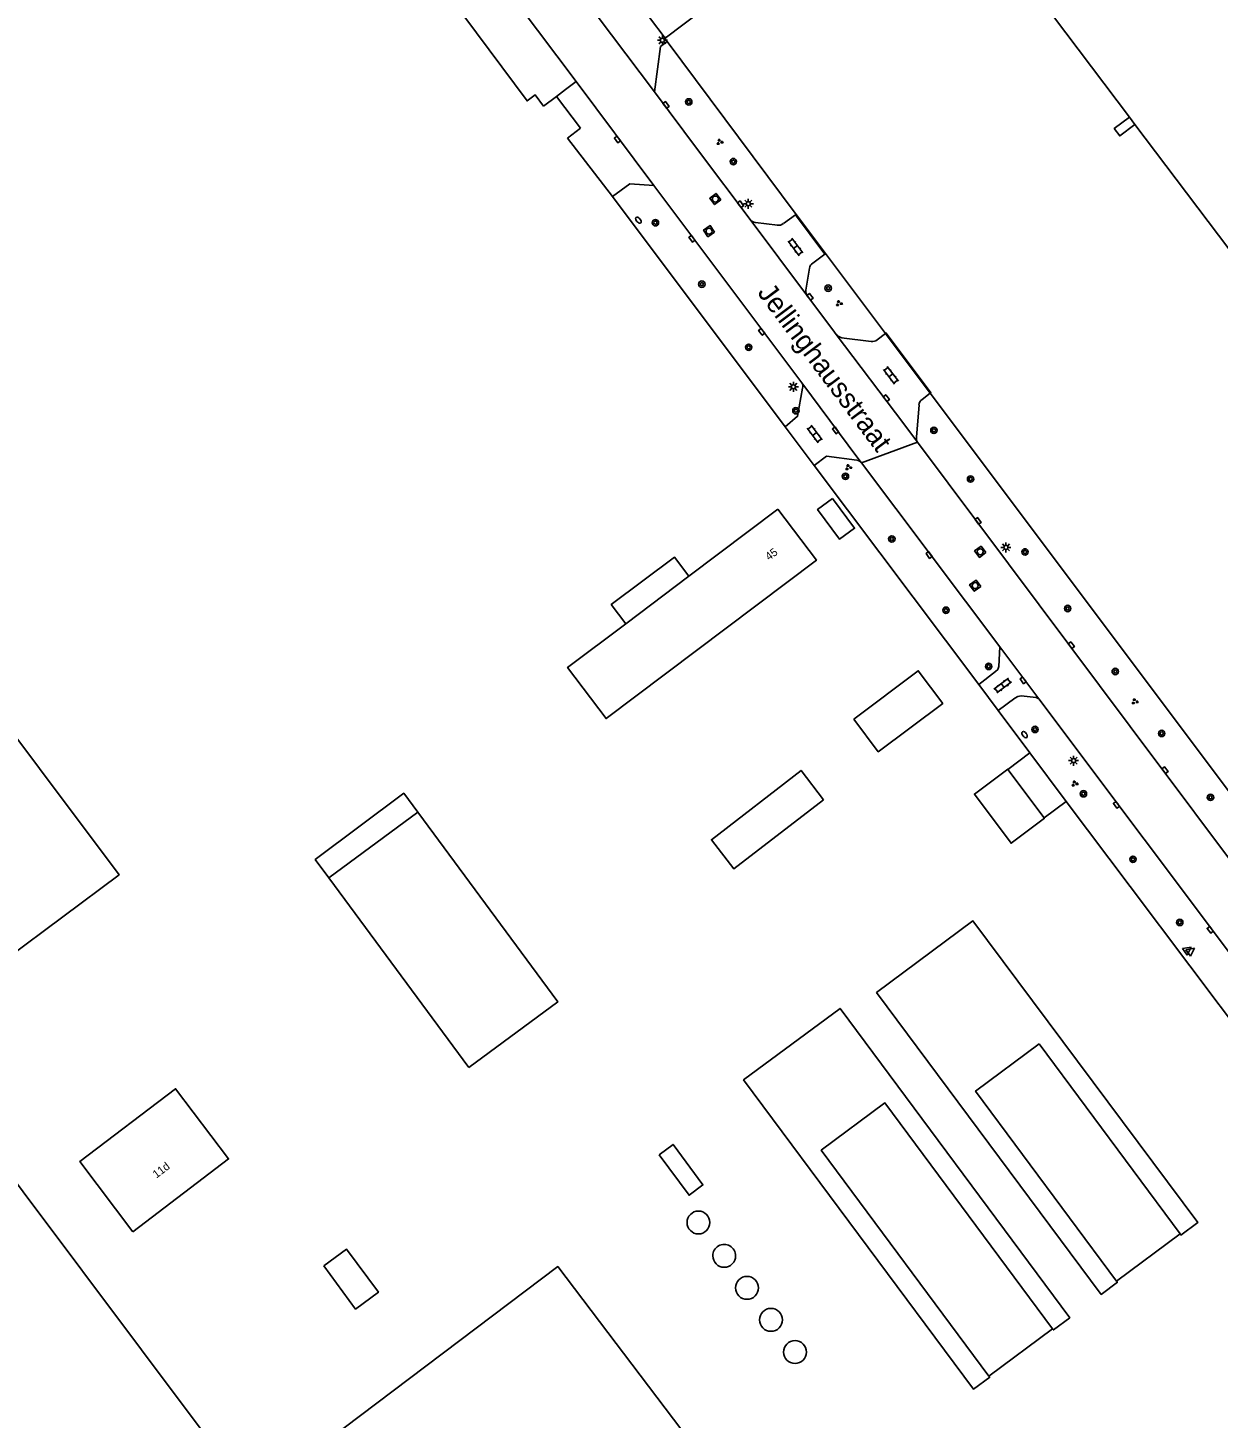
# Model space of a CAD drawing. Extents: x 130998 to 133001, y 398999 to 403002.
# Drawn here: x 131862.2 to 132011, y 400203.3 to 400377.1 of the extents above; entities that cross this region are included whole.
import ezdxf

# ---------------------------------------------------------------- set-up
doc = ezdxf.new("R2010")
doc.units = 0
for name, color, linetype in [('gg-afsc-erfafscheiding', 7, 'Continuous'), ('gg-afsc-hekwerk', 7, 'Continuous'), ('gg-anno-huisnummerreeks BGT', 7, 'Continuous'), ('gg-anno-openbare ruimte label', 7, 'Continuous'), ('gg-bbg-bijgebouw', 7, 'Continuous'), ('gg-bbg-gedigitaliseerde bebouwing', 7, 'Continuous'), ('gg-bbg-gedigitaliseerde bijgebouw', 7, 'Continuous'), ('gg-bbg-hoofdgebouw', 7, 'Continuous'), ('gg-bbg-luifel en loopbrug', 7, 'Continuous'), ('gg-bbg-opslagtank', 7, 'Continuous'), ('gg-knt-trap', 7, 'Continuous'), ('gg-knt-verharding', 7, 'Continuous'), ('gg-knt-verharding nz', 7, 'Continuous'), ('gg-kwrk-keermuur', 7, 'Continuous'), ('gt-grn-groengrens', 7, 'Continuous'), ('gt-grn-weggrens', 7, 'Continuous'), ('gt-symb-boom', 7, 'Continuous'), ('gt-symb-brandkraan', 7, 'Continuous'), ('gt-symb-groenvak', 7, 'Continuous'), ('gt-symb-klinker verharding', 7, 'Continuous'), ('gt-symb-kolk', 7, 'Continuous'), ('gt-symb-lichtmast', 7, 'Continuous'), ('gt-symb-rioolschacht', 7, 'Continuous'), ('gt-symb-waterafsluiter', 7, 'Continuous')]:
    doc.layers.add(name, color=color, linetype=linetype)

# ---------------------------------------------------------------- blocks, each defined once
blk = doc.blocks.new('gt0-WAFSL')
at = {"layer": 'gt-symb-waterafsluiter'}
for p, q in [((-0.5, -0.33), (0, 0.67)), ((0, 0.67), (0.5, -0.33)), ((0.5, -0.33), (-0.5, -0.33))]:
    blk.add_line(p, q, dxfattribs=at)
blk = doc.blocks.new('gt0-KOLK')
at = {"layer": 'gt-symb-kolk'}
blk.add_lwpolyline([(0, 0), (0.37, 0), (0.37, 0.4), (-0.38, 0.4), (-0.38, 0), (0, 0)], dxfattribs=at)
blk = doc.blocks.new('gt0-BOOM')
at = {"layer": 'gt-symb-boom'}
for radius in [0.4, 0.2]:
    blk.add_circle((0, 0), radius, dxfattribs=at)
blk = doc.blocks.new('gt0-GRVAK')
at = {"layer": 'gt-symb-groenvak'}
for p, q in [((-0.11, 0.19), (-0.23, 0.24)), ((-0.18, 0.15), (0.09, 0.15)), ((-0.09, 0.21), (-0.16, 0.32)), ((-0.05, 0.21), (-0.05, 0.39)), ((0, 0.21), (0.06, 0.32)), ((0.01, 0.19), (0.13, 0.24)), ((0.26, -0.05), (0.2, 0.06)), ((0.3, -0.05), (0.3, 0.13)), ((0.35, -0.05), (0.41, 0.06)), ((-0.24, -0.23), (-0.36, -0.18)), ((-0.32, -0.26), (-0.05, -0.26)), ((-0.23, -0.21), (-0.29, -0.09)), ((-0.18, -0.2), (-0.18, -0.02)), ((-0.14, -0.21), (-0.07, -0.09)), ((-0.12, -0.23), (0, -0.18)), ((0.24, -0.07), (0.12, -0.02)), ((0.17, -0.11), (0.44, -0.11)), ((0.37, -0.07), (0.49, -0.02))]:
    blk.add_line(p, q, dxfattribs=at)
blk = doc.blocks.new('gt0-LMAST')
at = {"layer": 'gt-symb-lichtmast'}
for p, q in [((-0.18, 0.17), (-0.45, 0.44)), ((-0.01, 0.25), (-0.01, 0.62)), ((0.17, 0.17), (0.44, 0.44)), ((-0.26, 0), (-0.63, 0)), ((-0.18, -0.18), (-0.45, -0.45)), ((-0.01, -0.25), (-0.01, -0.63)), ((0.44, -0.45), (0.17, -0.18)), ((0.24, 0), (0.62, 0))]:
    blk.add_line(p, q, dxfattribs=at)
blk.add_circle((-0.01, 0), 0.25, dxfattribs=at)
blk = doc.blocks.new('gt0-BR')
at = {"layer": 'gt-symb-brandkraan'}
for centre, radius, start, end in [((-0.24, 0), 0.206, 107.5669, 252.4331), ((0.6, -2.66), 3, 106.892, 107.5669), ((0, -0.69), 0.938, 73.108, 106.892), ((-0.6, -2.66), 3, 72.4331, 73.108), ((0.24, 0), 0.206, 287.567, 72.4331), ((0.6, 2.66), 3, 252.4331, 253.108), ((0, 0.69), 0.938, 253.108, 286.8921), ((-0.6, 2.66), 3, 286.8921, 287.567)]:
    blk.add_arc(centre, radius, start, end, dxfattribs=at)
blk = doc.blocks.new('gt0-RS')
at = {"layer": 'gt-symb-rioolschacht'}
blk.add_lwpolyline([(-0.5, -0.5), (0.5, -0.5), (0.5, 0.5), (-0.5, 0.5)], close=True, dxfattribs=at)
blk.add_circle((0, 0), 0.375, dxfattribs=at)
blk = doc.blocks.new('gt0-KL1')
at = {"layer": 'gt-symb-klinker verharding'}
for p, q in [((-1.15, 0.3), (1.15, 0.3)), ((-1, -0.3), (-1, 0.3)), ((-0.5, 0.3), (-0.5, 0.45)), ((0, -0.3), (0, 0.3)), ((0.5, 0.3), (0.5, 0.45)), ((1, -0.3), (1, 0.3)), ((-1.15, -0.3), (1.15, -0.3)), ((-0.5, -0.45), (-0.5, -0.3)), ((0.5, -0.45), (0.5, -0.3))]:
    blk.add_line(p, q, dxfattribs=at)

msp = doc.modelspace()

# ---------------------------------------------------------------- linework, layer by layer
at = {"layer": 'gg-afsc-erfafscheiding'}
msp.add_line((131935.27, 400355.97), (131929.67, 400363.3), dxfattribs=at)
at = {"layer": 'gg-afsc-hekwerk'}
for p, q in [((131958.25, 400353.75), (131942.09, 400375.35)), ((131956.86, 400327.2), (131935.27, 400355.97)), ((131961.9, 400348.87), (131958.25, 400353.75)), ((131969.4, 400338.85), (131961.9, 400348.87)), ((131975, 400331.39), (131969.4, 400338.85)), ((132022.03, 400268.65), (131975, 400331.39)), ((131960.48, 400322.38), (131956.86, 400327.2)), ((131981.05, 400294.97), (131960.48, 400322.38)), ((131983.48, 400291.73), (131981.05, 400294.97)), ((131987.46, 400286.43), (131983.48, 400291.73)), ((131987.46, 400286.43), (131984.7, 400284.37)), ((131987.46, 400286.43), (131992, 400280.38)), ((131992, 400280.38), (131989.23, 400278.31)), ((131992, 400280.38), (132000, 400269.72)), ((132000, 400269.72), (132040.85, 400215.32))]:
    msp.add_line(p, q, dxfattribs=at)
for points in [[(131941.84, 400375.77), (131965.6, 400393.74), (131961.47, 400399.02)], [(131942.09, 400375.35), (131941.8, 400375.73), (131941.84, 400375.77)]]:
    msp.add_lwpolyline(points, dxfattribs=at)
at = {"layer": 'gg-bbg-bijgebouw'}
for p, q in [((131989.23, 400278.31), (131984.7, 400284.37)), ((131988.6, 400250.06), (132006.22, 400226.32)), ((132006.22, 400226.32), (131998.28, 400220.42)), ((131982.33, 400208.55), (131990.28, 400214.45))]:
    msp.add_line(p, q, dxfattribs=at)
for points in [[(131989.23, 400278.31), (131989.26, 400278.27), (131985.1, 400275.15), (131980.51, 400281.29), (131984.67, 400284.41), (131984.7, 400284.37)], [(131990.28, 400214.45), (131969.32, 400242.68), (131961.37, 400236.78), (131982.33, 400208.55)]]:
    msp.add_lwpolyline(points, dxfattribs=at)
at = {"layer": 'gg-bbg-gedigitaliseerde bebouwing'}
msp.add_lwpolyline([(131854.12, 400241.52), (131883.88, 400201.87), (131845.08, 400172.72)], dxfattribs=at)
at = {"layer": 'gg-bbg-gedigitaliseerde bijgebouw'}
for p, q in [((131910.95, 400279.02), (131899.84, 400270.83)), ((131899.84, 400270.83), (131917.32, 400247.13))]:
    msp.add_line(p, q, dxfattribs=at)
for points in [[(131917.32, 400247.13), (131928.43, 400255.32), (131910.95, 400279.02)], [(131998.28, 400220.42), (131980.65, 400244.16), (131988.6, 400250.06)]]:
    msp.add_lwpolyline(points, dxfattribs=at)
at = {"layer": 'gg-bbg-hoofdgebouw'}
for p, q in [((132000.58, 400365), (131999.9, 400365.9)), ((132061.51, 400284.22), (132000.58, 400365)), ((131944.8, 400308.52), (131955.95, 400316.91)), ((131936.93, 400302.59), (131944.8, 400308.52))]:
    msp.add_line(p, q, dxfattribs=at)
for points in [[(131999.9, 400365.9), (131977.56, 400395.52), (131996.91, 400410.15)], [(131955.95, 400316.91), (131960.76, 400310.52), (131934.47, 400290.73), (131929.66, 400297.12), (131936.93, 400302.59)], [(131829.51, 400300.69), (131843.56, 400311.23), (131873.6, 400271.2), (131859.54, 400260.68), (131829.51, 400300.69)], [(131875.33, 400226.59), (131868.68, 400235.36), (131880.66, 400244.45), (131887.3, 400235.69), (131875.33, 400226.59)], [(131930.73, 400159.61), (131899.7, 400200.52), (131928.43, 400222.23), (131959.46, 400181.32)]]:
    msp.add_lwpolyline(points, dxfattribs=at)
at = {"layer": 'gg-bbg-luifel en loopbrug'}
for points in [[(131962.78, 400318.24), (131965.53, 400314.51), (131963.67, 400313.14), (131960.92, 400316.87), (131962.78, 400318.24)], [(131936.93, 400302.59), (131935.13, 400304.98), (131943.01, 400310.91), (131944.8, 400308.52)], [(131965.44, 400290.67), (131973.5, 400296.7), (131976.55, 400292.62), (131968.49, 400286.59), (131965.44, 400290.67)], [(131961.66, 400280.58), (131958.85, 400284.24), (131947.64, 400275.59), (131950.46, 400271.94), (131961.66, 400280.58)], [(131910.95, 400279.02), (131909.18, 400281.39), (131898.12, 400273.11), (131899.84, 400270.83)], [(131998.28, 400220.42), (131998.39, 400220.27), (131996.36, 400218.76), (131968.29, 400256.47), (131980.32, 400265.43), (132008.42, 400227.72), (132006.33, 400226.17), (132006.22, 400226.32)], [(131982.33, 400208.55), (131982.44, 400208.4), (131980.41, 400206.9), (131951.67, 400245.57), (131963.72, 400254.51), (131992.43, 400215.83), (131990.39, 400214.31), (131990.28, 400214.45)], [(131941.1, 400236.21), (131944.84, 400231.15), (131946.58, 400232.43), (131942.85, 400237.5), (131941.1, 400236.21)], [(131899.18, 400222.32), (131903.16, 400216.92), (131906.01, 400219.02), (131902.02, 400224.42), (131899.18, 400222.32)]]:
    msp.add_lwpolyline(points, dxfattribs=at)
at = {"layer": 'gg-bbg-opslagtank'}
for centre, start, end in [((131946.02, 400227.74), 0, 180), ((131946.02, 400227.74), 180, 0), ((131949.24, 400223.57), 359.9201, 179.9601), ((131949.24, 400223.57), 179.9601, 359.9201), ((131952.09, 400219.57), 0, 180), ((131952.09, 400219.57), 180, 360), ((131955.08, 400215.57), 0, 180), ((131955.08, 400215.57), 180, 0), ((131958.09, 400211.54), 0.02, 179.98), ((131958.09, 400211.54), 180.02, 359.98)]:
    msp.add_arc(centre, 1.43, start, end, dxfattribs=at)
at = {"layer": 'gg-knt-trap'}
msp.add_lwpolyline([(131999.9, 400365.9), (131998, 400364.47), (131998.68, 400363.57), (132000.58, 400365)], dxfattribs=at)
at = {"layer": 'gg-knt-verharding'}
for p, q in [((131941.84, 400375.77), (131929.57, 400392.12)), ((131928.26, 400368.5), (131926.65, 400367.29)), ((131946.02, 400361.71), (131940.52, 400369.07)), ((131952.47, 400353.1), (131946.02, 400361.71)), ((131940.45, 400357.38), (131958.93, 400332.7)), ((131956.63, 400352.6), (131958.17, 400353.7)), ((131958.17, 400353.7), (131961.81, 400348.8)), ((131953.13, 400352.74), (131955.88, 400352.4)), ((131961.81, 400348.8), (131960.3, 400347.67)), ((131959.89, 400347.02), (131959.46, 400344.26)), ((131962.8, 400339.31), (131959.65, 400343.51)), ((131962.8, 400339.31), (131963.25, 400338.73)), ((131963.92, 400338.34), (131967.61, 400337.86)), ((131968.37, 400338.07), (131969.4, 400338.85)), ((131975, 400331.39), (131973.97, 400330.62)), ((131973.59, 400329.93), (131973.27, 400325.92)), ((131966.42, 400322.69), (131983.71, 400299.69)), ((131988.57, 400293.21), (132044.77, 400218.22))]:
    msp.add_line(p, q, dxfattribs=at)
for points in [[(131926.65, 400367.29), (131925.63, 400368.68), (131924.61, 400367.94), (131902.55, 400397.59), (131903.8, 400398.53)], [(131940.52, 400369.07), (131941.28, 400374.72), (131942.09, 400375.35)], [(131940.45, 400357.38), (131937.45, 400357.56), (131935.27, 400355.97)], [(131969.4, 400338.85), (131969.49, 400338.92), (131975.07, 400331.45), (131975, 400331.39)], [(131956.86, 400327.2), (131958.41, 400328.52), (131959.04, 400332.02)], [(131973.4, 400325.29), (132000, 400289.73), (132016.03, 400268.34)], [(131965.8, 400323.03), (131962.04, 400323.54), (131960.48, 400322.38)], [(131981.05, 400294.97), (131983.16, 400296.61), (131983.44, 400296.88), (131983.57, 400297.24), (131983.71, 400299.69)], [(131983.48, 400291.73), (131985.56, 400293.29), (131985.94, 400293.49), (131986.36, 400293.58), (131988.22, 400293.37), (131988.57, 400293.21)]]:
    msp.add_lwpolyline(points, dxfattribs=at)
for centre, radius, start, end in [((131953.23, 400353.69), 0.958, 217.9728, 263.8882), ((131956.02, 400353.4), 1.01, 261.9257, 306.9732), ((131960.84, 400346.88), 0.957, 124.3274, 171.646), ((131960.52, 400344.13), 1.07, 172.9882, 215.6208), ((131964.07, 400339.36), 1.03, 217.81, 262.0796), ((131967.75, 400338.86), 1, 261.989, 308.24), ((131958.05, 400332.21), 1.01, 349.2336, 28.8941), ((131974.6, 400329.83), 1.02, 128.4467, 174.2288), ((131974.2, 400325.8), 0.945, 172.4755, 212.4087), ((131965.71, 400322.14), 0.899, 37.8178, 84.0415)]:
    msp.add_arc(centre, radius, start, end, dxfattribs=at)
at = {"layer": 'gg-knt-verharding nz'}
for p, q in [((131924.13, 400390.87), (131940.52, 400369.07)), ((131929.39, 400369.35), (131928.26, 400368.5)), ((131930.72, 400370.35), (131929.39, 400369.35)), ((131930.72, 400370.35), (131940.45, 400357.38)), ((131928.26, 400368.5), (131931.29, 400364.54)), ((131952.47, 400353.1), (131959.65, 400343.51)), ((131963.25, 400338.73), (131971.68, 400327.59)), ((131958.93, 400332.7), (131965.96, 400323.3)), ((131971.68, 400327.59), (131973.4, 400325.29)), ((131965.96, 400323.3), (131966.42, 400322.69)), ((131983.71, 400299.69), (131988.57, 400293.21))]:
    msp.add_line(p, q, dxfattribs=at)
msp.add_lwpolyline([(131907.51, 400401.31), (131911.53, 400395.92), (131930.72, 400370.35)], dxfattribs=at)
at = {"layer": 'gg-kwrk-keermuur'}
msp.add_line((131929.67, 400363.3), (131931.29, 400364.54), dxfattribs=at)
at = {"layer": 'gt-grn-groengrens'}
for p, q in [((131958.25, 400353.75), (131958.17, 400353.7)), ((131961.9, 400348.87), (131961.81, 400348.8))]:
    msp.add_line(p, q, dxfattribs=at)
at = {"layer": 'gt-grn-weggrens'}
msp.add_line((131966.42, 400322.69), (131973.4, 400325.29), dxfattribs=at)

# ---------------------------------------------------------------- block references
at = {"layer": 'gt-symb-boom'}
for p in [(131944.81, 400367.81), (131950.38, 400360.35), (131940.64, 400352.71), (131946.44, 400345.03), (131962.23, 400344.53), (131952.3, 400337.14), (131958.2, 400329.21), (131975.45, 400326.76), (131964.39, 400321.01), (131980.03, 400320.67), (131970.19, 400313.18), (131986.84, 400311.56), (131976.96, 400304.27), (131992.17, 400304.49), (131982.29, 400297.25), (131998.12, 400296.61), (131988.09, 400289.37), (132003.92, 400288.87), (131994.14, 400281.33), (132010.02, 400280.88), (132000.33, 400273.14), (132006.18, 400265.25)]:
    msp.add_blockref('gt0-BOOM', p, dxfattribs=at)
at = {"layer": 'gt-symb-brandkraan'}
for p, rotation in [((131938.52, 400353.03), 130.253185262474), ((131986.78, 400288.73), 126.37706752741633)]:
    msp.add_blockref('gt0-BR', p, dxfattribs=dict(at, rotation=rotation))
at = {"layer": 'gt-symb-groenvak'}
for p in [(131948.66, 400362.8), (131963.58, 400342.62), (131964.76, 400322.12), (132000.55, 400292.86), (131993.04, 400282.59)]:
    msp.add_blockref('gt0-GRVAK', p, dxfattribs=at)
at = {"layer": 'gt-symb-klinker verharding'}
for p, rotation in [((131958.15, 400349.68), 126.66359246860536), ((131970.07, 400333.64), 127.44283634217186), ((131960.55, 400326.3), -53.130102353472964), ((131984.05, 400294.86), 36.95012773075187)]:
    msp.add_blockref('gt0-KL1', p, dxfattribs=dict(at, rotation=rotation))
at = {"layer": 'gt-symb-kolk'}
for p, rotation in [((131941.81, 400367.31), -53.33640752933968), ((131936.05, 400363.24), 126.50328298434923), ((131951.12, 400354.9), -53.37059891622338), ((131945.36, 400350.83), 126.58342113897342), ((131959.81, 400343.32), -52.71774480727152), ((131954.08, 400339.2), 127.68393139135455), ((131969.35, 400330.66), -52.92387968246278), ((131963.31, 400326.88), 126.74379669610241), ((131980.82, 400315.31), -53.049872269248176), ((131975.01, 400311.3), 126.78969964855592), ((131992.47, 400299.77), -52.55716365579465), ((131986.76, 400295.62), 126.5373863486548), ((132004.18, 400284.16), -53.17596648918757), ((131998.43, 400280.06), 126.45721008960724), ((132010.14, 400264.45), 126.5834211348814)]:
    msp.add_blockref('gt0-KOLK', p, dxfattribs=dict(at, rotation=rotation))
at = {"layer": 'gt-symb-lichtmast'}
for p in [(131941.52, 400375.51), (131952.26, 400355.09), (131957.89, 400332.2), (131984.46, 400312.13), (131992.92, 400285.47)]:
    msp.add_blockref('gt0-LMAST', p, dxfattribs=at)
at = {"layer": 'gt-symb-rioolschacht'}
for p, rotation in [((131948.13, 400355.67), 127.5685920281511), ((131947.35, 400351.65), 123.57881372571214), ((131981.24, 400311.58), 126.70953402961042), ((131980.61, 400307.35), 125.59763149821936)]:
    msp.add_blockref('gt0-RS', p, dxfattribs=dict(at, rotation=rotation))
at = {"layer": 'gt-symb-waterafsluiter', "rotation": -53.130102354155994}
for p in [(132007.09, 400261.77), (132007.5, 400261.64)]:
    msp.add_blockref('gt0-WAFSL', p, dxfattribs=at)

# ---------------------------------------------------------------- texts
at = {"layer": 'gg-anno-huisnummerreeks BGT'}
for s, rotation, p in [('45', 37, (131954.84, 400310.44)), ('11d', 37.2, (131878.27, 400233.22))]:
    msp.add_text(s, height=1, rotation=rotation, dxfattribs=at).set_placement(p)
at = {"layer": 'gg-anno-openbare ruimte label'}
msp.add_text('Jellinghausstraat', height=2.5, rotation=306.9, dxfattribs=at).set_placement((131953.3, 400343.95))

doc.saveas('drawing.dxf')
